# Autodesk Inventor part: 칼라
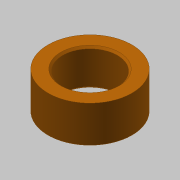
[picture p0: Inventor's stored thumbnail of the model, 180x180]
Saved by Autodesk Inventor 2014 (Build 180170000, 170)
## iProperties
Created: 2015-09
Part Number: 칼라
Document SubType Name: Modeling
Designer: mduedu
Density: 1 g/cm^3
Material: 스테인리스강
Appearance: 주황색
Author: mduedu
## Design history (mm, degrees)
node "작업 평면1"
node "작업 평면2"
sketch "스케치1"
  geometry: C1 r 7.5 at (0, 0); C2 r 11.5 at (0, 0); 1 further point
  constraints: 2 centre point, 2 coincident
  dimensions: "d0" = 15 diameter of C1; "d1" = 23 diameter of C2
extrude "돌출1" new body sketch "스케치1" stored distance "d2" = 9.85; taper "d3" = 0 deg
chamfer "모따기1" distance "d4" = 0.5; stored, may be unused: second distance "d5" = 2, angle "d6" = 45 deg
node "솔리드1"
